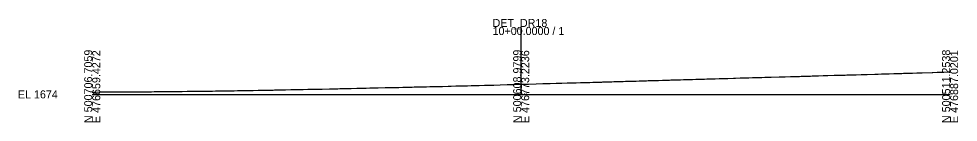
# Model space of a CAD drawing. Extents: x -26 to 303, y -10 to 3627.
# Drawn here: x -25.7 to 302.8, y -9.7 to 26.4 of the extents above; entities that cross this region are included whole.
import ezdxf

# ---------------------------------------------------------------- set-up
doc = ezdxf.new("R2010")
doc.units = 0
for name, color, linetype in [('Exist Cross Section Cell', 7, 'Continuous'), ('Exist XS Center Line Elevation Label', 7, 'Continuous'), ('Exist XS Ground Line', 7, 'Continuous')]:
    doc.layers.add(name, color=color, linetype=linetype)

msp = doc.modelspace()

# ---------------------------------------------------------------- linework, layer by layer
at = {"layer": 'Exist Cross Section Cell'}
for p, q in [((150, 0), (150, 23.52)), ((0, 0), (150, 0)), ((150, 0), (300, 0))]:
    msp.add_line(p, q, dxfattribs=at)
at = {"layer": 'Exist XS Ground Line'}
msp.add_lwpolyline([(0, 0.83), (1.19, 0.83), (2.48, 0.84), (3.07, 0.84), (3.53, 0.84), (6.06, 0.85), (6.47, 0.85), (6.83, 0.86), (8.36, 0.86), (10.13, 0.88), (11.81, 0.89), (13.88, 0.9), (15.46, 0.91), (16.72, 0.92), (17.59, 0.93), (18.87, 0.94), (20.01, 0.95), (20.76, 0.95), (21.62, 0.96), (22.48, 0.97), (23.31, 0.97), (25.41, 0.99), (26.04, 1), (26.56, 1), (27.81, 1.02), (29.07, 1.03), (29.51, 1.03), (29.89, 1.04), (31.39, 1.05), (33.19, 1.07), (33.75, 1.08), (36.61, 1.11), (36.96, 1.12), (38.46, 1.14), (39.78, 1.15), (40.58, 1.16), (42, 1.18), (43.07, 1.2), (43.77, 1.21), (44.49, 1.22), (45.49, 1.23), (46.37, 1.25), (47.36, 1.26), (48.47, 1.28), (49.08, 1.29), (49.66, 1.29), (50.84, 1.31), (52.38, 1.33), (52.96, 1.34), (54.37, 1.37), (56.25, 1.4), (57.98, 1.43), (59.78, 1.46), (62.84, 1.52), (63.3, 1.53), (63.7, 1.54), (65.01, 1.57), (66.16, 1.59), (66.64, 1.6), (67.6, 1.62), (69.4, 1.66), (70.63, 1.68), (71.47, 1.7), (72.13, 1.72), (72.73, 1.73), (73.77, 1.74), (75.38, 1.78), (76.02, 1.8), (79.27, 1.86), (80.36, 1.88), (82.97, 1.94), (84.59, 1.96), (85.89, 1.99), (86.64, 2.01), (88.08, 2.03), (89.18, 2.06), (89.75, 2.08), (90.56, 2.09), (92.49, 2.14), (92.83, 2.14), (93.96, 2.17), (94.42, 2.18), (95.18, 2.2), (95.83, 2.21), (97.06, 2.24), (98.2, 2.27), (99.09, 2.29), (100, 2.3), (102.39, 2.36), (104.47, 2.4), (105.94, 2.44), (107.27, 2.46), (108.64, 2.5), (109.44, 2.52), (110.32, 2.54), (111.9, 2.56), (112.54, 2.58), (113.77, 2.61), (114.65, 2.63), (115.4, 2.65), (116.88, 2.69), (118.11, 2.71), (119.77, 2.75), (121.27, 2.79), (122.19, 2.81), (122.51, 2.81), (124.41, 2.86), (125.08, 2.88), (125.48, 2.89), (127.16, 2.93), (128.59, 2.97), (129.02, 2.98), (129.81, 3), (130.14, 3), (131.2, 3.03), (132.5, 3.06), (133.99, 3.1), (134.98, 3.12), (135.32, 3.13), (137.19, 3.18), (137.58, 3.19), (137.92, 3.2), (140.43, 3.27), (142.62, 3.33), (145.15, 3.41), (147.63, 3.47), (149.87, 3.54), (152.61, 3.61), (155.22, 3.68), (157.56, 3.75), (160.19, 3.82), (162.27, 3.88), (162.59, 3.89), (162.98, 3.9), (164.21, 3.93), (166.04, 3.98), (166.62, 3.99), (167.09, 4.01), (168.66, 4.05), (169.24, 4.06), (170.78, 4.11), (171.5, 4.13), (171.91, 4.14), (174.01, 4.2), (175.09, 4.23), (176.68, 4.27), (178.17, 4.32), (178.5, 4.33), (178.89, 4.34), (179.47, 4.36), (181.32, 4.41), (181.73, 4.43), (182.38, 4.44), (184.07, 4.49), (185.68, 4.54), (186.5, 4.56), (186.96, 4.57), (188.39, 4.62), (189.19, 4.64), (190.16, 4.67), (191.22, 4.7), (191.91, 4.72), (193.88, 4.78), (194.42, 4.8), (194.92, 4.81), (196.56, 4.86), (198.06, 4.9), (199.39, 4.95), (201.5, 5.01), (201.83, 5.02), (202.29, 5.04), (203.87, 5.08), (204.55, 5.1), (205.13, 5.12), (205.75, 5.13), (206.81, 5.16), (208.18, 5.2), (209.13, 5.23), (209.93, 5.25), (211.04, 5.28), (211.89, 5.3), (213.18, 5.34), (214.06, 5.36), (214.89, 5.39), (216.47, 5.43), (217.4, 5.46), (217.86, 5.47), (219.28, 5.51), (221.09, 5.56), (222.23, 5.59), (224.25, 5.65), (224.94, 5.67), (226.59, 5.72), (227.59, 5.75), (228.13, 5.77), (228.79, 5.78), (229.66, 5.81), (230.92, 5.84), (232.61, 5.88), (233.77, 5.92), (234.18, 5.93), (235.22, 5.96), (236.49, 6), (236.98, 6.01), (237.47, 6.02), (240.23, 6.1), (240.76, 6.12), (242.31, 6.15), (244.14, 6.21), (245.84, 6.25), (247.31, 6.3), (247.96, 6.32), (250.65, 6.39), (251.16, 6.41), (251.77, 6.43), (252.95, 6.46), (253.95, 6.49), (255.63, 6.55), (256.47, 6.57), (257.2, 6.59), (259.45, 6.65), (260.56, 6.68), (261.85, 6.72), (263.31, 6.76), (263.84, 6.78), (265.33, 6.83), (267.18, 6.88), (268.93, 6.93), (270.43, 6.97), (271.03, 6.99), (273.69, 7.07), (274.81, 7.1), (275.98, 7.13), (277.01, 7.16), (278.68, 7.2), (280.28, 7.25), (281.31, 7.29), (282.52, 7.32), (283.13, 7.34), (283.65, 7.35), (286.26, 7.43), (286.9, 7.45), (288.41, 7.49), (290.28, 7.54), (293.71, 7.65), (294.02, 7.66), (295.53, 7.71), (296.8, 7.74), (297.86, 7.77), (299.19, 7.82), (300, 7.84)], dxfattribs=at)

# ---------------------------------------------------------------- texts
at = {"layer": 'Exist Cross Section Cell'}
for s, p in [('DET_DR18', (140, 23.52)), ('10+00.0000 / 1', (140, 20.72)), ('EL 1674', (-26, -1.4))]:
    msp.add_text(s, height=2.8, dxfattribs=at).set_placement(p)
for s, p in [('N 500706.7059', (0, -10)), ('E 476659.4272', (2.8, -10)), ('N 500608.9799', (150, -10)), ('E 476773.2236', (152.8, -10)), ('N 500511.2538', (300, -10)), ('E 476887.0201', (302.8, -10))]:
    msp.add_text(s, height=2.8, rotation=90, dxfattribs=at).set_placement(p)
at = {"layer": 'Exist XS Center Line Elevation Label'}
msp.add_text('1677.54', height=0.75, dxfattribs=at).set_placement((148.31, -0.21))

doc.saveas('drawing.dxf')
